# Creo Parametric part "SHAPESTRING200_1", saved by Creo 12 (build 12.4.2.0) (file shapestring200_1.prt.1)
Units: Custom; MM, KILOGRAM, SECS

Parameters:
  PTC_WM_ITERATION = "0"
  PTC_WM_VERSION = "-.0"
  PTC_WM_LIFECYCLE_STATE = "In Work"
  PTC_WM_LIFECYCLE = "MO_CADDocument"
  PTC_WM_CREATED_BY = "Maximilian Roepper (Z0017RMS: MO)"
  PTC_WM_CREATED_ON = "18-Sep-26 11:36:42 AM"
  PTC_WM_MODIFIED_BY = "Maximilian Roepper (Z0017RMS: MO)"
  PTC_WM_MODIFIED_ON = "18-Sep-26 11:36:46 AM"
  PDMLINKNUMBER = "PDM000071455174"
  PTC_WM_NAME = "shapestring200_1.prt"
  PTC_WM_NUMBER = "PDM000071455174"

Other parameters: WEIGHT, WEIGHT_FACTOR, WEIGHT_ADD, _MASS_TEMP, _DIFF_TEMP, MC_ERRORS, SUPPLIER

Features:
  1. coordinate system
  2. datum plane "PRT_YZ"
  3. datum plane "PRT_XY"
  4. datum plane "PRT_XZ"
  5. coordinate system
  6. datum axis
  7. datum axis
  8. datum axis
  9. coordinate system
  10. imported feature

Other named items: PRT, SIEMENS_MO, DRW_VIEW_ORG, PRT_X, PRT_Y, PRT_Z, CS0, ROUGH_GROB

Layers: 00_STD_CSYS-KSYS, 01_STD_PLANES-EBENEN, 02_STD_AXES-ACHSEN, 03_STD_CSYS-KSYS, 24_IMPORT_FEAT-IMPORT_KE, INTFCLR

Surfaces: 1 plane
